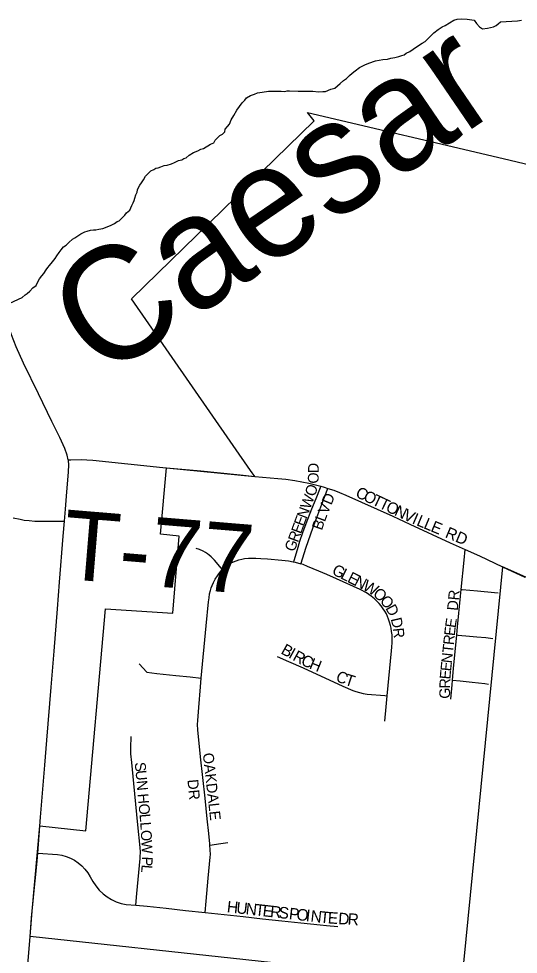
# Model space of a CAD drawing. Extents: x -13.9 to 69.1, y -25.2 to 26.1.
# Drawn here: x 2.853 to 3.245, y 17.221 to 17.954 of the extents above; entities that cross this region are included whole.
import ezdxf

# ---------------------------------------------------------------- set-up
doc = ezdxf.new("R2010")
doc.units = 0
for name, color, linetype in [('GM_X_City_Street', 7, 'Continuous'), ('GM_X_City_Street_Text', 7, 'Continuous'), ('GM_X_Corporation', 7, 'Continuous'), ('GM_X_County_Road', 7, 'Continuous'), ('GM_X_Major_River', 7, 'Continuous'), ('GM_X_Major_River_Text', 7, 'Continuous'), ('GM_X_Township_Road', 7, 'Continuous'), ('GM_X_Township_Road_Text', 7, 'Continuous')]:
    doc.layers.add(name, color=color, linetype=linetype)

msp = doc.modelspace()

# ---------------------------------------------------------------- linework, layer by layer
at = {"layer": 'GM_X_City_Street'}
for points in [[(3.03838, 17.59535), (3.05656, 17.59377), (3.06281, 17.59307), (3.06983, 17.59201), (3.0807, 17.58994)], [(3.0807, 17.58994), (3.08081, 17.58992), (3.09022, 17.58759)], [(3.06888, 17.52827), (3.06919, 17.52929), (3.07179, 17.5379), (3.07376, 17.54448), (3.07593, 17.55128), (3.07876, 17.55843), (3.0832, 17.56974), (3.08641, 17.57791), (3.08983, 17.58657), (3.09022, 17.58759)], [(3.07459, 17.52662), (3.07478, 17.52722), (3.07843, 17.53891), (3.08403, 17.55543), (3.08694, 17.56315), (3.09094, 17.57349), (3.09524, 17.58456), (3.09577, 17.58594)], [(3.09022, 17.58759), (3.09271, 17.58686), (3.09577, 17.58594)], [(3.09577, 17.58594), (3.10025, 17.58449), (3.10471, 17.5826), (3.10969, 17.58058), (3.14668, 17.56403), (3.16009, 17.55772), (3.19175, 17.54327), (3.20338, 17.53802)], [(3.01302, 17.52218), (3.01204, 17.52329), (3.00836, 17.52777), (3.00675, 17.52961), (3.00424, 17.5321), (3.00268, 17.53352), (3.00123, 17.53465), (2.9996, 17.53566), (2.99785, 17.53655), (2.99496, 17.5379), (2.99246, 17.53872)], [(3.20024, 17.50662), (3.20255, 17.52971), (3.20338, 17.53802)], [(3.20338, 17.53802), (3.21477, 17.53288), (3.23275, 17.52438)], [(3.01302, 17.52218), (3.01461, 17.52378), (3.01616, 17.52501), (3.0178, 17.52615), (3.01991, 17.5274), (3.02174, 17.52826), (3.02386, 17.5291), (3.02594, 17.52987), (3.02825, 17.53048), (3.03027, 17.53085), (3.03333, 17.53117), (3.0358, 17.53125), (3.03906, 17.53128), (3.04305, 17.53101), (3.04844, 17.53063), (3.05955, 17.52956), (3.06485, 17.52898), (3.06852, 17.52836), (3.06888, 17.52827)], [(2.99625, 17.43715), (3.00032, 17.47803), (3.002, 17.49682), (3.00245, 17.50012), (3.00293, 17.5033), (3.00358, 17.5058), (3.00418, 17.50787), (3.00496, 17.50983), (3.00603, 17.5122), (3.00738, 17.51461), (3.00898, 17.51725), (3.01024, 17.51896), (3.01177, 17.52095), (3.01302, 17.52218)], [(3.06888, 17.52827), (3.07179, 17.52753), (3.07459, 17.52662)], [(3.14228, 17.42321), (3.14574, 17.45849), (3.14594, 17.46134), (3.14612, 17.46496), (3.14616, 17.46805), (3.14607, 17.47097), (3.14568, 17.47359), (3.14525, 17.47616), (3.14476, 17.47849), (3.14417, 17.48087), (3.14335, 17.48339), (3.14259, 17.48537), (3.14156, 17.48741), (3.14032, 17.48969), (3.13897, 17.49156), (3.13744, 17.49378), (3.13582, 17.4957), (3.13392, 17.4978), (3.13223, 17.49937), (3.1297, 17.5014), (3.12796, 17.50264), (3.12596, 17.50395), (3.12097, 17.50653), (3.10247, 17.51502), (3.09494, 17.51838), (3.0886, 17.52108), (3.0796, 17.52473), (3.07629, 17.52608), (3.07459, 17.52662)], [(3.19677, 17.47095), (3.19737, 17.4772), (3.19972, 17.50139), (3.20024, 17.50662)], [(3.20024, 17.50662), (3.20093, 17.50656), (3.21305, 17.50543), (3.22648, 17.50417), (3.22926, 17.50392)], [(3.19344, 17.43552), (3.19425, 17.44473), (3.19677, 17.47095)], [(3.19677, 17.47095), (3.19784, 17.47085), (3.20684, 17.47003), (3.21255, 17.46951), (3.21955, 17.46887), (3.22506, 17.46829)], [(3.05586, 17.4541), (3.06478, 17.45017), (3.07637, 17.44507), (3.10745, 17.43074), (3.11518, 17.42747), (3.11767, 17.42655), (3.12053, 17.42573), (3.12338, 17.42502), (3.12648, 17.42464), (3.14049, 17.42337), (3.14228, 17.42321)], [(2.9476, 17.44821), (2.95378, 17.44164), (2.96143, 17.44085), (2.97652, 17.43925), (2.98758, 17.43807), (2.99625, 17.43715)], [(3.00317, 17.30605), (3.00308, 17.30702), (3.00228, 17.31531), (3.00106, 17.32683), (2.99933, 17.34304), (2.99762, 17.35925), (2.99589, 17.37547), (2.99365, 17.39653), (2.99344, 17.40065), (2.99356, 17.40378), (2.99439, 17.41411), (2.9957, 17.4303), (2.99625, 17.43715)], [(3.19206, 17.42052), (3.19311, 17.43173), (3.19344, 17.43552)], [(3.19344, 17.43552), (3.19953, 17.43489), (3.20878, 17.43391), (3.21893, 17.43285), (3.22169, 17.43246)], [(3.14034, 17.4034), (3.14143, 17.41453), (3.14228, 17.42321)], [(2.94494, 17.25916), (2.94577, 17.26819), (2.94832, 17.29574), (2.94843, 17.29697), (2.94861, 17.30061), (2.94842, 17.30425), (2.94668, 17.32209), (2.94508, 17.33836), (2.9435, 17.35458), (2.94191, 17.37081), (2.94123, 17.37784), (2.94105, 17.37996), (2.94099, 17.3821), (2.94099, 17.38243), (2.94129, 17.39125)], [(2.99932, 17.25328), (3.00017, 17.26229), (3.00184, 17.28016), (3.00339, 17.2968), (3.00352, 17.29874), (3.00344, 17.3024), (3.00317, 17.30605)], [(3.00317, 17.30605), (3.01182, 17.30736), (3.0172, 17.30817)], [(2.86816, 17.29988), (2.88352, 17.29864), (2.88699, 17.29814), (2.89039, 17.29724), (2.89368, 17.29597), (2.89683, 17.29432), (2.8998, 17.29232), (2.90255, 17.28999), (2.90506, 17.28737), (2.9073, 17.28447), (2.90924, 17.28134), (2.91124, 17.2776), (2.91359, 17.27411), (2.91628, 17.27092), (2.91928, 17.26804), (2.92254, 17.26553), (2.92602, 17.2634), (2.9297, 17.26169), (2.93353, 17.26041), (2.93746, 17.25957), (2.94494, 17.25916)], [(2.94494, 17.25916), (2.95386, 17.25819), (2.96895, 17.25656), (2.98404, 17.25493), (2.99932, 17.25328)], [(2.99932, 17.25328), (3.01422, 17.25166), (3.0293, 17.25003), (3.04439, 17.2484), (3.05948, 17.24677), (3.07457, 17.24513), (3.08965, 17.2435), (3.09454, 17.24297), (3.10361, 17.2422)]]:
    msp.add_lwpolyline(points, dxfattribs=at)
at = {"layer": 'GM_X_Corporation'}
msp.add_lwpolyline([(3.2881, 17.49986), (3.23275, 17.52438), (3.20043, 17.19781), (2.86218, 17.23447), (2.8637, 17.25422), (2.86975, 17.32112), (2.90578, 17.31737), (2.92111, 17.49154), (2.97408, 17.48812), (2.97905, 17.54843), (2.96443, 17.54989), (2.96898, 17.60212), (3.03838, 17.59535), (3.03512, 17.5999), (2.94158, 17.73445), (3.08504, 17.8742), (3.07968, 17.88075), (3.23311, 17.8445), (3.27165, 17.83539)], dxfattribs=at)
at = {"layer": 'GM_X_County_Road'}
for points in [[(2.89206, 17.60829), (2.8912, 17.61201), (2.88938, 17.61715), (2.8853, 17.62569), (2.87921, 17.63838), (2.86864, 17.65995), (2.85691, 17.68421), (2.85118, 17.69703), (2.84752, 17.70627), (2.844, 17.71684), (2.84055, 17.72933), (2.83802, 17.74086), (2.83618, 17.75193), (2.83478, 17.76429), (2.834, 17.7761), (2.83391, 17.78734), (2.8346, 17.80095), (2.83469, 17.80174)], [(2.88904, 17.56016), (2.88982, 17.56967), (2.89066, 17.5798), (2.89229, 17.59878), (2.89249, 17.60425), (2.89215, 17.60788), (2.89206, 17.60829)], [(2.86816, 17.29988), (2.87024, 17.32802), (2.87366, 17.36889), (2.87525, 17.38844), (2.87865, 17.42991), (2.88094, 17.45835), (2.88358, 17.49152), (2.88521, 17.51226), (2.88807, 17.54841), (2.88904, 17.56016)], [(2.86218, 17.23446), (2.86324, 17.24918), (2.86469, 17.2651), (2.86605, 17.27808), (2.86763, 17.29342), (2.86816, 17.29988)], [(2.85807, 17.1847), (2.86041, 17.21236), (2.86218, 17.23446)]]:
    msp.add_lwpolyline(points, dxfattribs=at)
at = {"layer": 'GM_X_Major_River'}
for points in [[(3.06369, 17.89761), (3.06572, 17.89759), (3.07247, 17.89751), (3.07821, 17.89745), (3.08395, 17.89738), (3.08833, 17.89697), (3.09171, 17.89729), (3.09374, 17.89727), (3.09814, 17.89904), (3.10119, 17.89973), (3.10527, 17.90332), (3.108, 17.90584), (3.11038, 17.90727), (3.11276, 17.90978), (3.11481, 17.91158), (3.11719, 17.91337), (3.12059, 17.91588), (3.12263, 17.91695), (3.12466, 17.91801), (3.12771, 17.91943), (3.13313, 17.92119), (3.13888, 17.92222), (3.1426, 17.92254), (3.14497, 17.92324), (3.14835, 17.92393), (3.1514, 17.92462), (3.15377, 17.92532), (3.15546, 17.92603), (3.15716, 17.9271), (3.15988, 17.92853), (3.1626, 17.93032), (3.16667, 17.93318), (3.16973, 17.93496), (3.17211, 17.93639), (3.17586, 17.94035), (3.17893, 17.94322), (3.18233, 17.94573), (3.18539, 17.94787), (3.18776, 17.94894), (3.19116, 17.95108), (3.19455, 17.95323), (3.19726, 17.95392), (3.2003, 17.95425), (3.20503, 17.95384), (3.21042, 17.95305), (3.21242, 17.95048), (3.21476, 17.94791), (3.21711, 17.94643), (3.22082, 17.94675), (3.2232, 17.94745), (3.22556, 17.94779), (3.2276, 17.94886), (3.2293, 17.95029), (3.231, 17.95173), (3.24451, 17.95267), (3.24756, 17.953)], [(2.82603, 17.72199), (2.85583, 17.73561), (2.85822, 17.73776), (2.85991, 17.73883), (2.86196, 17.74063), (2.86434, 17.74314), (2.86672, 17.74493), (2.86776, 17.74747), (2.86948, 17.75036), (2.87119, 17.75252), (2.87289, 17.75432), (2.87461, 17.75721), (2.87598, 17.75901), (2.87735, 17.76081), (2.87974, 17.76369), (2.88179, 17.76622), (2.88316, 17.76838), (2.88487, 17.77091), (2.88658, 17.77307), (2.88829, 17.77523), (2.89033, 17.77666), (2.89238, 17.77882), (2.89544, 17.78133), (2.89714, 17.7824), (2.9002, 17.78455), (2.9019, 17.78562), (2.90495, 17.78704), (2.90698, 17.78775), (2.90935, 17.78845), (2.91172, 17.78879), (2.91374, 17.78876), (2.91611, 17.7891), (2.91915, 17.78979), (2.9239, 17.79156), (2.92559, 17.79227), (2.92831, 17.79369), (2.93035, 17.79512), (2.93204, 17.79583), (2.93477, 17.79871), (2.93647, 17.80014), (2.93784, 17.80195), (2.94023, 17.8041), (2.94195, 17.80772), (2.94298, 17.80989), (2.94368, 17.81169), (2.94437, 17.81351), (2.94507, 17.81604), (2.9461, 17.81821), (2.94646, 17.82003), (2.94715, 17.82184), (2.94818, 17.82364), (2.94955, 17.82544), (2.95093, 17.82797), (2.95264, 17.83086), (2.95435, 17.83266), (2.95673, 17.83482), (2.9591, 17.83588), (2.9608, 17.83695), (2.96249, 17.8373), (2.96453, 17.838), (2.96724, 17.83906), (2.9696, 17.8394), (2.97299, 17.84045), (2.97537, 17.84152), (2.97842, 17.84294), (2.98113, 17.84363), (2.98282, 17.84471), (2.98452, 17.84505), (2.9869, 17.84721), (2.9903, 17.84935), (2.99369, 17.85076), (2.99606, 17.85183), (2.99809, 17.85253), (3.00353, 17.85574), (3.00624, 17.8568), (3.00727, 17.85897), (3.01102, 17.86257), (3.01306, 17.86364), (3.01476, 17.86543), (3.01512, 17.86761), (3.01683, 17.86977), (3.01854, 17.87157), (3.01992, 17.87483), (3.02198, 17.87844), (3.02438, 17.88241), (3.02643, 17.8853), (3.02849, 17.88819), (3.03054, 17.89034), (3.0319, 17.89215), (3.03496, 17.89393), (3.03801, 17.89499), (3.04038, 17.89605), (3.0441, 17.89674), (3.04917, 17.89741), (3.05457, 17.89735), (3.05896, 17.8973), (3.062, 17.89726), (3.06369, 17.89761)]]:
    msp.add_lwpolyline(points, dxfattribs=at)
at = {"layer": 'GM_X_Township_Road'}
for points in [[(2.89206, 17.60829), (2.89395, 17.60841), (2.90207, 17.60863), (2.9066, 17.60841), (2.91137, 17.60804), (2.96628, 17.60241), (2.96898, 17.60212)], [(2.96898, 17.60212), (2.99611, 17.59955), (3.02697, 17.59645), (3.03838, 17.59535)], [(2.84874, 17.56283), (2.85417, 17.56164), (2.85746, 17.5611), (2.86131, 17.56066), (2.86573, 17.5603), (2.87182, 17.5601), (2.88603, 17.56015), (2.88904, 17.56016)], [(3.23275, 17.52438), (3.25025, 17.51636)]]:
    msp.add_lwpolyline(points, dxfattribs=at)

# ---------------------------------------------------------------- texts
at = {"layer": 'GM_X_City_Street_Text'}
for s, height, rotation, p in [('D', 0.00842, 90.01428, (3.08853, 17.59779)), ('O', 0.00842, 88.7269, (3.08835, 17.58957)), ('O', 0.00849, 72.13415, (3.08542, 17.57903)), ('W', 0.00851, 69.68574, (3.08171, 17.56898)), ('D', 0.00853, 67.38622, (3.09838, 17.57233)), ('C', 0.00896, 334.64291, (3.1167, 17.57962)), ('O', 0.00896, 334.63694, (3.12281, 17.57673)), ('T', 0.00896, 334.67416, (3.1296, 17.57351)), ('V', 0.00853, 68.26998, (3.09547, 17.56504)), ('T', 0.00896, 334.65037, (3.13503, 17.57094)), ('O', 0.00896, 334.64436, (3.14045, 17.56837)), ('N', 0.00851, 69.70477, (3.07897, 17.56157)), ('N', 0.00896, 334.63694, (3.14724, 17.56515)), ('V', 0.00897, 335.16874, (3.1541, 17.5619)), ('I', 0.00898, 336.77544, (3.16113, 17.55865)), ('E', 0.00851, 69.6828, (3.07458, 17.54971)), ('E', 0.00851, 69.6828, (3.07677, 17.55563)), ('B', 0.00851, 70.6473, (3.09093, 17.5525)), ('L', 0.00852, 69.49539, (3.09328, 17.55917)), ('L', 0.00898, 337.34088, (3.16465, 17.55714)), ('L', 0.00898, 337.37613, (3.17019, 17.55483)), ('E', 0.00898, 337.39989, (3.17572, 17.55252)), ('R', 0.00851, 69.69874, (3.07211, 17.54304)), ('RD', 0.008982, 337.29701, (3.18706, 17.54774)), ('G', 0.00851, 69.69046, (3.06937, 17.53563)), ('G', 0.00895, 333.25357, (3.09819, 17.51899)), ('L', 0.00895, 333.24079, (3.1049, 17.51561)), ('E', 0.00895, 333.23002, (3.11027, 17.5129)), ('N', 0.00895, 333.23804, (3.11564, 17.51019)), ('W', 0.00893, 330.46063, (3.12226, 17.50686)), ('O', 0.00882, 319.10071, (3.13043, 17.50228)), ('O', 0.00872, 310.09432, (3.13595, 17.49754)), ('DR', 0.008432, 84.41549, (3.19752, 17.4897)), ('D', 0.00858, 297.98119, (3.14064, 17.49204)), ('D', 0.00846, 283.17065, (3.14497, 17.48353)), ('E', 0.00844, 81.70545, (3.19591, 17.47614)), ('R', 0.00843, 276.13333, (3.14673, 17.4761)), ('R', 0.00843, 83.95652, (3.19447, 17.46277)), ('E', 0.00843, 83.68237, (3.19522, 17.46989)), ('B', 0.00893, 330.87292, (3.05823, 17.45674)), ('T', 0.00843, 83.96464, (3.1938, 17.45643)), ('I', 0.00893, 330.86626, (3.06415, 17.45344)), ('R', 0.00893, 330.83883, (3.06744, 17.4516)), ('N', 0.00843, 83.95106, (3.19296, 17.44851)), ('C', 0.00896, 334.39926, (3.07386, 17.44804)), ('H', 0.00899, 337.9359, (3.08045, 17.44491)), ('E', 0.00843, 84.04205, (3.1923, 17.44217)), ('C', 0.00897, 336.08344, (3.10119, 17.43522)), ('E', 0.00843, 85.03904, (3.19175, 17.43586)), ('T', 0.00901, 341.85983, (3.10819, 17.43217)), ('R', 0.00842, 88.66833, (3.19159, 17.42885)), ('G', 0.00842, 89.87808, (3.19158, 17.42092)), ('OAKDALE', 0.008434, 276.33701, (2.99754, 17.37804)), ('S', 0.00843, 275.21648, (2.94417, 17.37085)), ('U', 0.00843, 275.21092, (2.94475, 17.3645)), ('N', 0.00843, 275.22559, (2.94547, 17.35656)), ('DR', 0.008431, 275.30708, (2.9855, 17.35735)), ('H', 0.00843, 275.21092, (2.94642, 17.34624)), ('O', 0.00843, 275.21386, (2.94714, 17.3383)), ('L', 0.00843, 275.0622, (2.94786, 17.33037)), ('L', 0.00843, 273.96666, (2.94842, 17.32406)), ('O', 0.00843, 273.21179, (2.94886, 17.31774)), ('W', 0.00843, 273.112, (2.94931, 17.30978)), ('P', 0.00843, 267.78961, (2.94991, 17.29727)), ('L', 0.00843, 265.14031, (2.94968, 17.29102)), ('H', 0.00906, 353.64183, (3.01614, 17.25353)), ('U', 0.00906, 353.63265, (3.02351, 17.25271)), ('N', 0.00906, 353.63265, (3.03089, 17.25189)), ('T', 0.00906, 353.61385, (3.03826, 17.25107)), ('E', 0.00906, 353.63916, (3.04416, 17.25041)), ('R', 0.00906, 353.64371, (3.05006, 17.24975)), ('S', 0.00906, 353.64304, (3.0567, 17.24901)), ('P', 0.00906, 353.63916, (3.06481, 17.2481)), ('O', 0.00906, 353.64558, (3.07071, 17.24745)), ('I', 0.00906, 353.64424, (3.07808, 17.24663)), ('N', 0.00906, 353.64183, (3.08177, 17.24622)), ('T', 0.00906, 354.24042, (3.08923, 17.24539)), ('E', 0.00906, 355.93, (3.09539, 17.24477)), ('D', 0.00906, 356.37104, (3.1036, 17.2442)), ('R', 0.00906, 356.37376, (3.111, 17.24373))]:
    msp.add_text(s, height=height, rotation=rotation, dxfattribs=at).set_placement(p)
at = {"layer": 'GM_X_Major_River_Text'}
msp.add_text('Caesar', height=0.088832, rotation=34.30797, dxfattribs=at).set_placement((2.91827, 17.66961))
at = {"layer": 'GM_X_Township_Road_Text'}
msp.add_text('T-77', height=0.054361, rotation=355.26992, dxfattribs=at).set_placement((2.88609, 17.51518))

doc.saveas('drawing.dxf')
